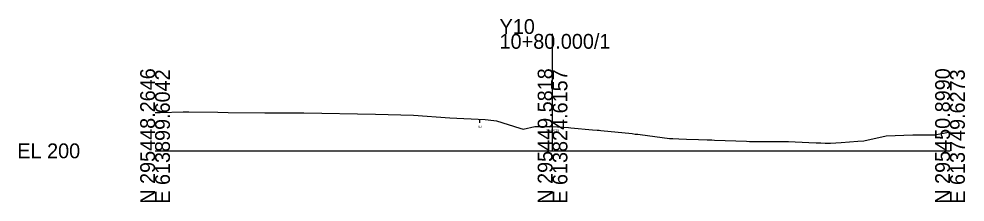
# Model space of a CAD drawing. Extents: x 517327 to 613901, y 114839 to 295511.
# Drawn here: x 517326.7 to 517505.2, y 116338.7 to 116373.3 of the extents above; entities that cross this region are included whole.
import ezdxf

# ---------------------------------------------------------------- set-up
doc = ezdxf.new("R2010")
doc.units = 0
for name, color, linetype in [('Old_Level_60', 7, 'Continuous'), ('Old_Level_63', 7, 'Continuous'), ('Old_Level_7', 7, 'Continuous'), ('Prop XS Exc Vertical Line 1', 7, 'Continuous')]:
    doc.layers.add(name, color=color, linetype=linetype)

msp = doc.modelspace()

# ---------------------------------------------------------------- linework, layer by layer
at = {"layer": 'Old_Level_63'}
for p, q in [((517427.36, 116348.36), (517427.36, 116370.45)), ((517352.36, 116348.36), (517427.36, 116348.36)), ((517427.36, 116348.36), (517502.36, 116348.36))]:
    msp.add_line(p, q, dxfattribs=at)
at = {"layer": 'Old_Level_7'}
for p, q in [((517352.36, 116355.6), (517352.72, 116355.6)), ((517352.72, 116355.6), (517353.29, 116355.61)), ((517353.29, 116355.61), (517357.69, 116355.73)), ((517357.69, 116355.73), (517358.73, 116355.72)), ((517358.73, 116355.72), (517364.22, 116355.65)), ((517364.22, 116355.65), (517366.16, 116355.63)), ((517366.16, 116355.63), (517373.06, 116355.56)), ((517373.06, 116355.56), (517380.1, 116355.56)), ((517380.1, 116355.56), (517380.46, 116355.56)), ((517380.46, 116355.56), (517393.98, 116355.28)), ((517393.98, 116355.28), (517401.1, 116355.09)), ((517401.1, 116355.09), (517407.98, 116354.57)), ((517407.98, 116354.57), (517414.62, 116354.27)), ((517414.62, 116354.27), (517415.22, 116354.21)), ((517415.22, 116354.21), (517416.81, 116354.04)), ((517416.81, 116354.04), (517421.18, 116352.67)), ((517421.18, 116352.67), (517421.8, 116352.44)), ((517421.8, 116352.44), (517424.01, 116352.94)), ((517424.01, 116352.94), (517427.31, 116352.94)), ((517427.31, 116352.94), (517430.36, 116352.77)), ((517430.36, 116352.77), (517430.79, 116352.72)), ((517430.79, 116352.72), (517434.91, 116352.34)), ((517434.91, 116352.34), (517435.77, 116352.28)), ((517435.77, 116352.28), (517436.16, 116352.25)), ((517436.16, 116352.25), (517436.48, 116352.21)), ((517436.48, 116352.21), (517442.39, 116351.62)), ((517499.5, 116351.39), (517502.36, 116351.98)), ((517442.39, 116351.62), (517442.93, 116351.53)), ((517442.93, 116351.53), (517443.45, 116351.49)), ((517443.45, 116351.49), (517443.9, 116351.45)), ((517443.9, 116351.45), (517449.44, 116350.72)), ((517449.44, 116350.72), (517450.03, 116350.7)), ((517450.03, 116350.7), (517451.19, 116350.63)), ((517451.19, 116350.63), (517452.64, 116350.58)), ((517452.64, 116350.58), (517454.89, 116350.49)), ((517454.89, 116350.49), (517456.54, 116350.42)), ((517456.54, 116350.42), (517457.05, 116350.41)), ((517457.05, 116350.41), (517457.4, 116350.41)), ((517457.4, 116350.41), (517457.95, 116350.4)), ((517457.95, 116350.4), (517463.98, 116350.18)), ((517463.98, 116350.18), (517464.55, 116350.15)), ((517464.55, 116350.15), (517465.38, 116350.12)), ((517465.38, 116350.12), (517470.12, 116350.12)), ((517470.12, 116350.12), (517470.85, 116350.12)), ((517470.85, 116350.12), (517471.87, 116350.12)), ((517471.87, 116350.12), (517475.75, 116349.92)), ((517481.84, 116349.92), (517484.99, 116350.17)), ((517484.99, 116350.17), (517486.11, 116350.24)), ((517486.11, 116350.24), (517490.34, 116351.17)), ((517490.34, 116351.17), (517495.35, 116351.36)), ((517495.35, 116351.36), (517499.5, 116351.39)), ((517475.75, 116349.92), (517477.12, 116349.87)), ((517477.12, 116349.87), (517477.99, 116349.87)), ((517477.99, 116349.87), (517478.82, 116349.84)), ((517478.82, 116349.84), (517479.8, 116349.84)), ((517479.8, 116349.84), (517481.84, 116349.92))]:
    msp.add_line(p, q, dxfattribs=at)
at = {"layer": 'Prop XS Exc Vertical Line 1'}
msp.add_line((517413.65, 116353.66), (517413.65, 116354.31), dxfattribs=at)

# ---------------------------------------------------------------- texts
at = {"layer": 'Old_Level_60'}
msp.add_text('204.573', height=0.5, dxfattribs=at).set_placement((517426.1, 116351.87))
at = {"layer": 'Old_Level_63'}
for s, p in [('Y10', (517417.36, 116370.45)), ('10+80.000/1', (517417.36, 116367.65)), ('EL 200', (517326.36, 116346.96))]:
    msp.add_text(s, height=2.8, dxfattribs=at).set_placement(p)
for s, p in [('N 295448.2646', (517352.36, 116338.36)), ('E 613899.6042', (517355.16, 116338.36)), ('N 295449.5818', (517427.36, 116338.36)), ('E 613824.6157', (517430.16, 116338.36)), ('N 295450.8990', (517502.36, 116338.36)), ('E 613749.6273', (517505.16, 116338.36))]:
    msp.add_text(s, height=2.8, rotation=90, dxfattribs=at).set_placement(p)
at = {"layer": 'Prop XS Exc Vertical Line 1'}
msp.add_text('E', height=0.5, rotation=90, dxfattribs=at).set_placement((517413.9, 116352.69))

doc.saveas('drawing.dxf')
